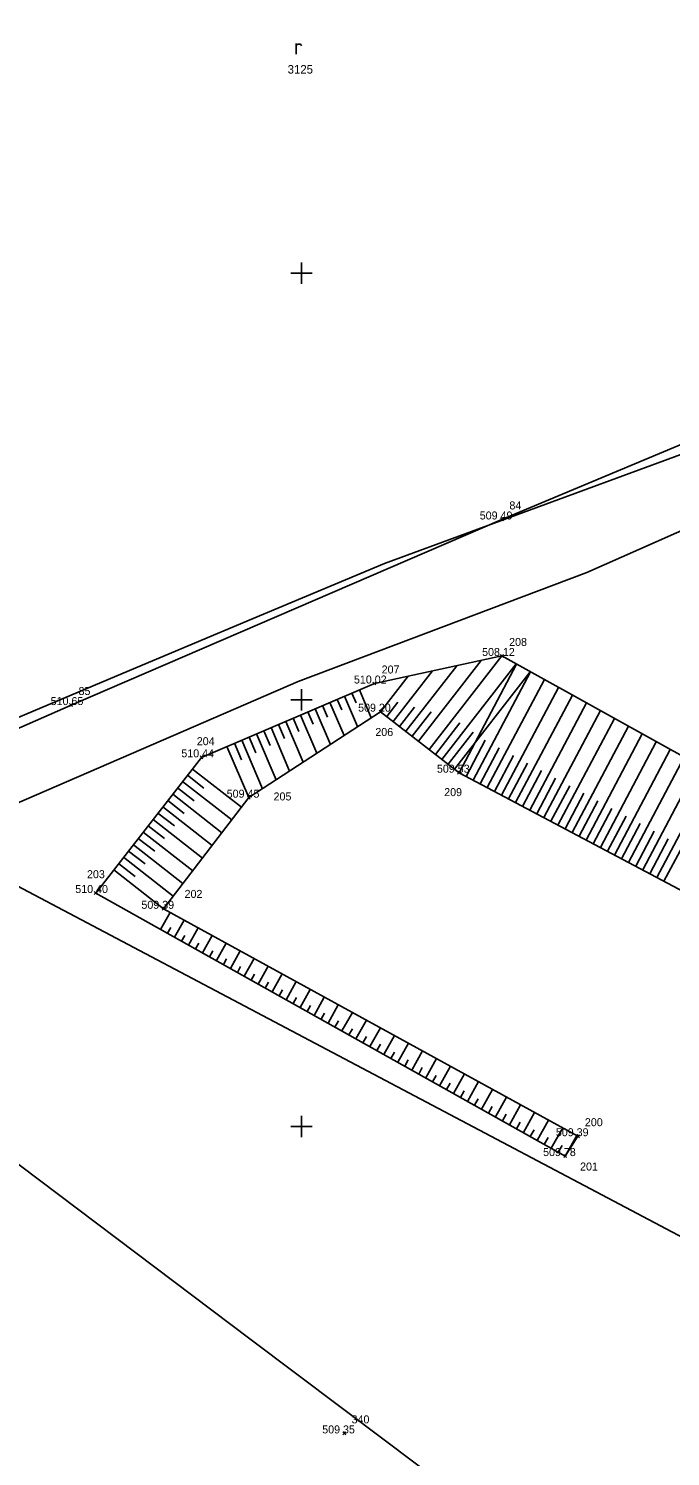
# Model space of a CAD drawing. Extents: x -408550 to -407654, y -1233019 to -1231230.
# Drawn here: x -408112.8 to -408082.7, y -1232035.5 to -1231968.5 of the extents above; entities that cross this region are included whole.
import ezdxf

# ---------------------------------------------------------------- set-up
doc = ezdxf.new("R2010")
doc.units = 0
for name, color, linetype in [('Level 1', 7, 'Continuous'), ('Level 12', 7, 'Continuous'), ('Level 13', 7, 'Continuous'), ('Level 23', 7, 'Continuous'), ('Level 26', 7, 'Continuous'), ('Level 4', 7, 'Continuous'), ('Level 40', 7, 'Continuous')]:
    doc.layers.add(name, color=color, linetype=linetype)

msp = doc.modelspace()

# ---------------------------------------------------------------- linework, layer by layer
at = {"layer": 'Level 1'}
for p, q in [((-408100, -1231979.5), (-408100, -1231980.5)), ((-408100.5, -1231980), (-408099.5, -1231980)), ((-408100.5, -1232000), (-408099.5, -1232000)), ((-408100, -1231999.5), (-408100, -1232000.5)), ((-408100.5, -1232020), (-408099.5, -1232020)), ((-408100, -1232019.5), (-408100, -1232020.5))]:
    msp.add_line(p, q, dxfattribs=at)
for points in [[(-408035.38, -1231969.67), (-408039.27, -1231971.28), (-408043.31, -1231972.94), (-408046.8, -1231974.23), (-408049.99, -1231975.4), (-408053.1, -1231976.54), (-408059.29, -1231978.81), (-408065.3, -1231981.01), (-408073.39, -1231984.6), (-408082.2, -1231988.5), (-408089.6, -1231991.22), (-408096.11, -1231993.62), (-408102.27, -1231996.2), (-408108.37, -1231998.76), (-408114.71, -1232001.42)], [(-408114.71, -1232001.42), (-408108.37, -1231998.76), (-408102.27, -1231996.2), (-408096.11, -1231993.62), (-408089.6, -1231991.22), (-408082.2, -1231988.5), (-408073.39, -1231984.6), (-408065.3, -1231981.01), (-408059.29, -1231978.81), (-408053.1, -1231976.54), (-408049.99, -1231975.4), (-408046.8, -1231974.23), (-408043.31, -1231972.94), (-408039.27, -1231971.28), (-408035.38, -1231969.67)], [(-408100.255, -1231969.742), (-408100.255, -1231969.242)], [(-408100.255, -1231969.342), (-408100.23, -1231969.309), (-408100.197, -1231969.282), (-408100.162, -1231969.269), (-408100.105, -1231969.267), (-408100.062, -1231969.274), (-408100.037, -1231969.292), (-408100.015, -1231969.317), (-408100.005, -1231969.342)], [(-408038.79, -1231974.16), (-408066.68, -1231985.23), (-408086.61, -1231994.04), (-408100.15, -1231999.15), (-408125.76, -1232010.23), (-408127.68, -1232010.95), (-408133.36, -1232013.08), (-408146.37, -1232017.08), (-408165.18, -1232022.99)], [(-408035.27, -1232074.4), (-408044.77, -1232071.09), (-408050.33, -1232069.15), (-408058.02, -1232063.36), (-408068.11, -1232055.77), (-408073.77, -1232051.51), (-408078.94, -1232047.62), (-408084.51, -1232043.43), (-408090.17, -1232039.17), (-408096, -1232034.78), (-408102.42, -1232029.95), (-408115.87, -1232019.83), (-408127.68, -1232010.95), (-408125.76, -1232010.23), (-408100.15, -1231999.15), (-408086.61, -1231994.04), (-408066.68, -1231985.23), (-408038.79, -1231974.16)], [(-408165.18, -1232022.99), (-408146.37, -1232017.08), (-408133.36, -1232013.08), (-408127.68, -1232010.95), (-408115.87, -1232019.83), (-408102.42, -1232029.95), (-408096, -1232034.78), (-408090.17, -1232039.17), (-408084.51, -1232043.43), (-408078.94, -1232047.62), (-408073.77, -1232051.51), (-408068.11, -1232055.77), (-408058.02, -1232063.36), (-408050.33, -1232069.15), (-408044.77, -1232071.09), (-408035.27, -1232074.4)]]:
    msp.add_lwpolyline(points, dxfattribs=at)
at = {"layer": 'Level 12'}
msp.add_lwpolyline([(-408037.34, -1231968.54), (-408046.88, -1231972.68), (-408058.05, -1231977.49), (-408065.95, -1231981.2), (-408066.72, -1231981.53), (-408081.67, -1231987.81), (-408090.6, -1231991.55), (-408110.81, -1232000.25), (-408118.15, -1232003.47), (-408117.7, -1232004.22), (-408114.75, -1232007.99), (-408081.23, -1232025.67), (-408056.73, -1232038.31), (-408035.18, -1232049.43)], dxfattribs=at)
at = {"layer": 'Level 13'}
for p, q in [((-408094.007, -1232002.334), (-408090.6, -1231997.95)), ((-408095.698, -1232001.02), (-408093.858, -1231998.653)), ((-408095.106, -1232001.48), (-408092.717, -1231998.407)), ((-408094.513, -1232001.941), (-408091.576, -1231998.16)), ((-408093.415, -1232002.794), (-408089.936, -1231998.318)), ((-408092.61, -1232003.42), (-408089.917, -1231998.329)), ((-408096.29, -1232000.56), (-408094.999, -1231998.899)), ((-408092.823, -1232003.255), (-408089.272, -1231998.686)), ((-408091.947, -1232003.771), (-408089.261, -1231998.692)), ((-408091.284, -1232004.121), (-408088.605, -1231999.056)), ((-408098.32, -1231999.982), (-408098.109, -1232000.478)), ((-408097.975, -1231999.835), (-408097.367, -1232001.262)), ((-408097.63, -1231999.688), (-408097.436, -1232000.143)), ((-408097.285, -1231999.541), (-408096.729, -1232000.846)), ((-408090.621, -1232004.472), (-408087.949, -1231999.42)), ((-408089.958, -1232004.823), (-408087.293, -1231999.784)), ((-408099.7, -1232000.571), (-408099.454, -1232001.147)), ((-408099.355, -1232000.424), (-408098.642, -1232002.094)), ((-408099.01, -1232000.277), (-408098.781, -1232000.813)), ((-408098.665, -1232000.13), (-408098.005, -1232001.678)), ((-408095.994, -1232000.79), (-408095.473, -1232000.119)), ((-408095.402, -1232001.25), (-408094.698, -1232000.344)), ((-408094.81, -1232001.711), (-408093.923, -1232000.569)), ((-408089.295, -1232005.173), (-408086.637, -1232000.147)), ((-408088.632, -1232005.524), (-408085.981, -1232000.511)), ((-408101.424, -1232001.307), (-408100.556, -1232003.342)), ((-408101.08, -1232001.16), (-408100.799, -1232001.817)), ((-408100.735, -1232001.013), (-408099.918, -1232002.926)), ((-408100.39, -1232000.865), (-408100.127, -1232001.482)), ((-408100.045, -1232000.718), (-408099.28, -1232002.51)), ((-408093.711, -1232002.564), (-408092.565, -1232001.089)), ((-408087.969, -1232005.875), (-408085.324, -1232000.875)), ((-408087.306, -1232006.225), (-408084.668, -1232001.239)), ((-408102.804, -1232001.895), (-408101.832, -1232004.174)), ((-408102.459, -1232001.748), (-408102.144, -1232002.487)), ((-408102.114, -1232001.601), (-408101.194, -1232003.758)), ((-408101.769, -1232001.454), (-408101.472, -1232002.152)), ((-408093.119, -1232003.024), (-408091.949, -1232001.519)), ((-408092.279, -1232003.595), (-408091.383, -1232001.902)), ((-408086.643, -1232006.576), (-408084.012, -1232001.602)), ((-408085.98, -1232006.927), (-408083.356, -1232001.966)), ((-408103.494, -1232002.19), (-408102.47, -1232004.59)), ((-408103.149, -1232002.043), (-408102.817, -1232002.822)), ((-408091.616, -1232003.946), (-408090.722, -1232002.257)), ((-408090.953, -1232004.297), (-408090.062, -1232002.612)), ((-408085.317, -1232007.278), (-408082.7, -1232002.33)), ((-408084.654, -1232007.628), (-408082.044, -1232002.694)), ((-408105.116, -1232003.247), (-408102.816, -1232005.041)), ((-408090.29, -1232004.647), (-408089.401, -1232002.967)), ((-408089.627, -1232004.998), (-408088.74, -1232003.322)), ((-408083.991, -1232007.979), (-408081.388, -1232003.057)), ((-408105.578, -1232003.838), (-408103.273, -1232005.636)), ((-408105.347, -1232003.542), (-408104.58, -1232004.14)), ((-408088.964, -1232005.349), (-408088.08, -1232003.677)), ((-408088.301, -1232005.699), (-408087.419, -1232004.032)), ((-408083.329, -1232008.33), (-408080.732, -1232003.421)), ((-408106.039, -1232004.43), (-408103.73, -1232006.231)), ((-408105.808, -1232004.134), (-408105.04, -1232004.733)), ((-408087.638, -1232006.05), (-408086.758, -1232004.387)), ((-408106.731, -1232005.317), (-408105.959, -1232005.918)), ((-408106.5, -1232005.021), (-408104.186, -1232006.825)), ((-408106.269, -1232004.725), (-408105.5, -1232005.326)), ((-408086.975, -1232006.401), (-408086.098, -1232004.742)), ((-408086.312, -1232006.752), (-408085.437, -1232005.097)), ((-408107.192, -1232005.908), (-408106.419, -1232006.511)), ((-408106.961, -1232005.612), (-408104.643, -1232007.42)), ((-408085.649, -1232007.102), (-408084.776, -1232005.452)), ((-408084.986, -1232007.453), (-408084.116, -1232005.807)), ((-408107.653, -1232006.5), (-408106.879, -1232007.103)), ((-408107.423, -1232006.204), (-408105.1, -1232008.015)), ((-408084.323, -1232007.804), (-408083.455, -1232006.162)), ((-408083.66, -1232008.154), (-408082.794, -1232006.518)), ((-408108.114, -1232007.091), (-408107.339, -1232007.696)), ((-408107.884, -1232006.795), (-408105.557, -1232008.61)), ((-408082.997, -1232008.505), (-408082.134, -1232006.873)), ((-408108.806, -1232007.978), (-408106.47, -1232009.8)), ((-408108.576, -1232007.682), (-408107.798, -1232008.288)), ((-408108.345, -1232007.387), (-408106.013, -1232009.205)), ((-408106.607, -1232010.764), (-408106.162, -1232009.969)), ((-408106.28, -1232010.947), (-408106.131, -1232010.681)), ((-408105.953, -1232011.13), (-408105.505, -1232010.329)), ((-408105.299, -1232011.497), (-408104.847, -1232010.69)), ((-408105.626, -1232011.313), (-408105.476, -1232011.046)), ((-408104.644, -1232011.863), (-408104.189, -1232011.051)), ((-408104.971, -1232011.68), (-408104.821, -1232011.41)), ((-408104.317, -1232012.046), (-408104.165, -1232011.775)), ((-408103.99, -1232012.229), (-408103.532, -1232011.411)), ((-408103.335, -1232012.596), (-408102.874, -1232011.772)), ((-408103.663, -1232012.413), (-408103.51, -1232012.139)), ((-408103.008, -1232012.779), (-408102.854, -1232012.504)), ((-408102.681, -1232012.962), (-408102.216, -1232012.132)), ((-408102.027, -1232013.329), (-408101.559, -1232012.493)), ((-408102.354, -1232013.145), (-408102.199, -1232012.868)), ((-408101.699, -1232013.512), (-408101.543, -1232013.233)), ((-408101.372, -1232013.695), (-408100.901, -1232012.854)), ((-408100.718, -1232014.061), (-408100.244, -1232013.214)), ((-408101.045, -1232013.878), (-408100.888, -1232013.597)), ((-408100.391, -1232014.245), (-408100.232, -1232013.962)), ((-408100.063, -1232014.428), (-408099.586, -1232013.575)), ((-408099.409, -1232014.794), (-408098.928, -1232013.936)), ((-408099.736, -1232014.611), (-408099.577, -1232014.326)), ((-408099.082, -1232014.978), (-408098.921, -1232014.691)), ((-408098.755, -1232015.161), (-408098.271, -1232014.296)), ((-408098.1, -1232015.527), (-408097.613, -1232014.657)), ((-408098.428, -1232015.344), (-408098.266, -1232015.055)), ((-408097.446, -1232015.894), (-408096.955, -1232015.017)), ((-408096.792, -1232016.26), (-408096.298, -1232015.378)), ((-408097.773, -1232015.71), (-408097.61, -1232015.42)), ((-408097.119, -1232016.077), (-408096.955, -1232015.784)), ((-408096.137, -1232016.626), (-408095.64, -1232015.739)), ((-408096.464, -1232016.443), (-408096.299, -1232016.149)), ((-408095.81, -1232016.81), (-408095.644, -1232016.513)), ((-408095.483, -1232016.993), (-408094.982, -1232016.099)), ((-408094.828, -1232017.359), (-408094.325, -1232016.46)), ((-408095.156, -1232017.176), (-408094.988, -1232016.878)), ((-408094.501, -1232017.543), (-408094.333, -1232017.242)), ((-408094.174, -1232017.726), (-408093.667, -1232016.821)), ((-408093.52, -1232018.092), (-408093.009, -1232017.181)), ((-408093.847, -1232017.909), (-408093.677, -1232017.607)), ((-408093.192, -1232018.275), (-408093.022, -1232017.971)), ((-408092.865, -1232018.459), (-408092.352, -1232017.542)), ((-408092.211, -1232018.825), (-408091.694, -1232017.902)), ((-408092.538, -1232018.642), (-408092.366, -1232018.336)), ((-408091.884, -1232019.008), (-408091.711, -1232018.7)), ((-408091.556, -1232019.191), (-408091.036, -1232018.263)), ((-408090.902, -1232019.558), (-408090.379, -1232018.624)), ((-408091.229, -1232019.375), (-408091.056, -1232019.065)), ((-408090.248, -1232019.924), (-408089.721, -1232018.984)), ((-408089.593, -1232020.291), (-408089.064, -1232019.345)), ((-408090.575, -1232019.741), (-408090.4, -1232019.429)), ((-408089.92, -1232020.108), (-408089.745, -1232019.794)), ((-408088.939, -1232020.657), (-408088.406, -1232019.706)), ((-408088.284, -1232021.024), (-408087.748, -1232020.066)), ((-408089.266, -1232020.474), (-408089.089, -1232020.158)), ((-408088.612, -1232020.84), (-408088.434, -1232020.522)), ((-408087.63, -1232021.39), (-408087.091, -1232020.427)), ((-408087.957, -1232021.207), (-408087.778, -1232020.887))]:
    msp.add_line(p, q, dxfattribs=at)
msp.add_lwpolyline([(-408035.39, -1232034.45), (-408049.04, -1232027.43), (-408052.82, -1232025.69), (-408070.1, -1232016.12), (-408080.7, -1232009.72), (-408092.61, -1232003.42), (-408096.29, -1232000.56), (-408102.47, -1232004.59), (-408106.47, -1232009.8), (-408087.03, -1232020.46), (-408087.63, -1232021.39), (-408109.65, -1232009.06), (-408104.69, -1232002.7), (-408096.58, -1231999.24), (-408090.6, -1231997.95), (-408079.85, -1232003.91), (-408067.57, -1232011.48), (-408051.16, -1232021.6), (-408044.47, -1232014.71), (-408042.95, -1232014.34), (-408048.62, -1232025.83), (-408034.51, -1232032.58)], dxfattribs=at)
at = {"layer": 'Level 23'}
for points in [[(-408090.531, -1231991.619), (-408090.669, -1231991.481)], [(-408090.669, -1231991.619), (-408090.531, -1231991.481)], [(-408090.531, -1231998.019), (-408090.669, -1231997.881)], [(-408090.669, -1231998.019), (-408090.531, -1231997.881)], [(-408096.511, -1231999.309), (-408096.649, -1231999.171)], [(-408096.649, -1231999.309), (-408096.511, -1231999.171)], [(-408110.741, -1232000.319), (-408110.879, -1232000.181)], [(-408110.879, -1232000.319), (-408110.741, -1232000.181)], [(-408096.221, -1232000.629), (-408096.359, -1232000.491)], [(-408096.359, -1232000.629), (-408096.221, -1232000.491)], [(-408104.621, -1232002.769), (-408104.759, -1232002.631)], [(-408104.759, -1232002.769), (-408104.621, -1232002.631)], [(-408092.541, -1232003.489), (-408092.679, -1232003.351)], [(-408092.679, -1232003.489), (-408092.541, -1232003.351)], [(-408102.401, -1232004.659), (-408102.539, -1232004.521)], [(-408102.539, -1232004.659), (-408102.401, -1232004.521)], [(-408109.581, -1232009.129), (-408109.719, -1232008.991)], [(-408109.719, -1232009.129), (-408109.581, -1232008.991)], [(-408106.401, -1232009.869), (-408106.539, -1232009.731)], [(-408106.539, -1232009.869), (-408106.401, -1232009.731)], [(-408086.961, -1232020.529), (-408087.099, -1232020.391)], [(-408087.099, -1232020.529), (-408086.961, -1232020.391)], [(-408087.561, -1232021.459), (-408087.699, -1232021.321)], [(-408087.699, -1232021.459), (-408087.561, -1232021.321)], [(-408097.921, -1232034.459), (-408098.059, -1232034.321)], [(-408098.059, -1232034.459), (-408097.921, -1232034.321)]]:
    msp.add_lwpolyline(points, dxfattribs=at)
at = {"layer": 'Level 4'}
msp.add_lwpolyline([(-408035.27, -1232074.4), (-408044.77, -1232071.09), (-408050.33, -1232069.15), (-408058.02, -1232063.36), (-408068.11, -1232055.77), (-408073.77, -1232051.51), (-408078.94, -1232047.62), (-408084.51, -1232043.43), (-408090.17, -1232039.17), (-408096, -1232034.78), (-408102.42, -1232029.95), (-408115.87, -1232019.83), (-408127.68, -1232010.95), (-408125.76, -1232010.23), (-408100.15, -1231999.15), (-408086.61, -1231994.04), (-408066.68, -1231985.23), (-408038.79, -1231974.16)], dxfattribs=at)

# ---------------------------------------------------------------- texts
at = {"layer": 'Level 1'}
msp.add_text('3125', height=0.4, dxfattribs=at).set_placement((-408100.649, -1231970.651))
at = {"layer": 'Level 26'}
for s, p in [('84', (-408090.246, -1231991.08)), ('208', (-408090.26, -1231997.48)), ('207', (-408096.24, -1231998.77)), ('85', (-408110.456, -1231999.78)), ('206', (-408096.535, -1232001.701)), ('204', (-408104.911, -1232002.132)), ('205', (-408101.309, -1232004.721)), ('209', (-408093.306, -1232004.518)), ('203', (-408110.06, -1232008.365)), ('202', (-408105.483, -1232009.289)), ('200', (-408086.706, -1232019.99)), ('201', (-408086.932, -1232022.067)), ('340', (-408097.65, -1232033.92))]:
    msp.add_text(s, height=0.375, dxfattribs=at).set_placement(p)
at = {"layer": 'Level 40'}
for s, p in [('509 49', (-408091.638, -1231991.55)), ('508 12', (-408091.528, -1231997.95)), ('510 02', (-408097.54, -1231999.24)), ('510 65', (-408111.764, -1232000.25)), ('509 20', (-408097.343, -1232000.56)), ('510 44', (-408105.634, -1232002.7)), ('509 53', (-408093.647, -1232003.42)), ('509 45', (-408103.507, -1232004.59)), ('510 40', (-408110.61, -1232009.06)), ('509 39', (-408107.508, -1232009.8)), ('509 39', (-408088.068, -1232020.46)), ('509 78', (-408088.667, -1232021.39)), ('509 35', (-408099.027, -1232034.39))]:
    msp.add_text(s, height=0.375, dxfattribs=at).set_placement(p)

doc.saveas('drawing.dxf')
